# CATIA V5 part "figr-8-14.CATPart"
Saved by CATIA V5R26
Part number: Part1
Bounding box of the stored display mesh (mm): x -13.793 to 92.338, y -14.211 to 51.229, z 54 to 123.392
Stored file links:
  D:\_Deepak\CATIA\CATIA V5-6R2016_Deepak\Resources\Part files\Partfiles\c08_catia_v5_6r2016_prt\figr-8-14.CATPart
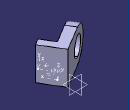
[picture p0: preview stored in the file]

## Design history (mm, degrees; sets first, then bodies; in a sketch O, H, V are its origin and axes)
AxisSystem1: origin (79.4802, 0.6447, 69), X (-0.515, 0.8572, 0), Y (0, 0, 1), Z (-0.8572, -0.515, 0)
AxisSystem2: origin (64.029, 26.3597, 54), X (0.515, -0.8572, 0), Y (-0.8572, -0.515, 0), Z (0, 0, 1)
Body1 (main body)
  Sketch1 on yz-plane, origin (0, 0, 0), H (0, 1, 0), V (0, 0, 1)
    point P1 (-104.4861, 0)
    line L1 (-104.4861, 0) -> (-104.4861, 44.267)
    arc A1 centre (-69.7903, 44.267) radius 34.6958 from (-104.4861, 44.267) to (-35.0946, 44.267) cw
    line L2 (-35.0946, 44.267) -> (-35.0946, 0)
    point P5 (-35.0946, 0)
    line L3 (-35.0946, 0) -> (-104.4861, 0)
    circle A2 centre (-69.7903, 44.267) radius 19.5413
    coincidence: P1 H, P5 H
    vertical: L1 V
    tangency: A1 L1, L2 A1
    horizontal: L3 H
  Pad1: profile Sketch1, direction (1, 0, 0), length 20
  Sketch2 on face of Pad1, origin (0, 0, 0), H (0, -1, 0), V (0, 0, 1)
    point P1 (35.0946, 0)
    line L1 (35.0946, 0) -> (104.4861, 0)
    line L2 (104.4861, 0) -> (104.4861, -15)
    line L3 (104.4861, -15) -> (35.0946, -15)
    line L4 (35.0946, -15) -> (35.0946, 0)
    reference projected line E1 (35.0946, 0) -> (35.0946, 44.267) from edge [face of Pad1 | face of Pad1]
    reference projected line E2 (104.4861, 44.267) -> (104.4861, 0) from edge [face of Pad1 | face of Pad1]
    distance L3 L1 = 15
    coincidence: P1 H, L4 E1, L2 E2
    horizontal: L1 H, L3 H
    vertical: L2 V, L4 V
  Pad2: profile Sketch2, direction (1, 0, 0), length 50
  Translate1: ToTransfor Pad2, Direction xy-plane, Length 69
  Rotate1: ToTransfor Translate1, Axis edge, Angle 121
  AxisToAxis1: ToTransfor Rotate1, AxisOrigin AxisSystem1, Axis AxisSystem2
